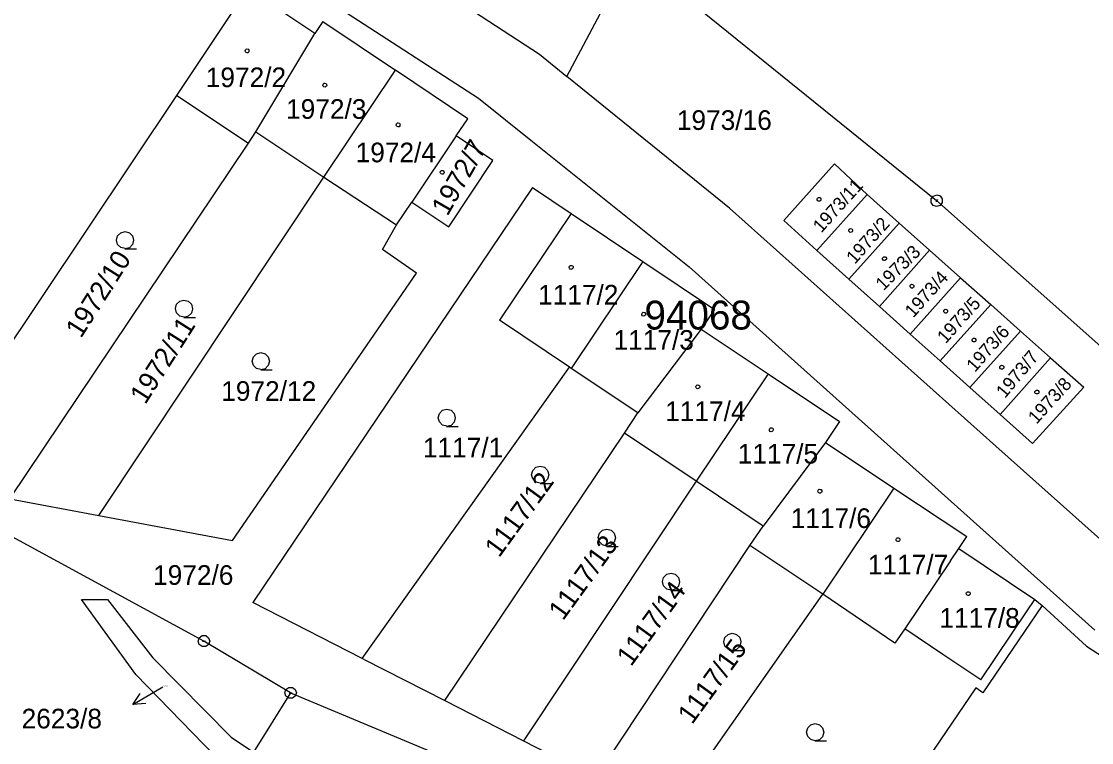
# Model space of a CAD drawing. Extents: x -806774 to -803680, y -1151731 to -1150053.
# Drawn here: x -804116.6 to -804023.9, y -1150162 to -1150099.6 of the extents above; entities that cross this region are included whole.
import ezdxf

# ---------------------------------------------------------------- set-up
doc = ezdxf.new("R2010")
doc.units = 0
for name, color, linetype in [('1', 7, 'Continuous'), ('11', 7, 'Continuous'), ('12', 7, 'Continuous'), ('2', 7, 'Continuous'), ('3', 7, 'Continuous'), ('5', 7, 'Continuous'), ('7', 7, 'Continuous'), ('8', 7, 'Continuous')]:
    doc.layers.add(name, color=color, linetype=linetype)

msp = doc.modelspace()

# ---------------------------------------------------------------- linework, layer by layer
at = {"layer": '1'}
for p, q in [((-804085.95, -1150093.17), (-804071.72, -1150102.49)), ((-804069.36, -1150104.41), (-804063.74, -1150093.81)), ((-804063.74, -1150093.81), (-804037.36, -1150115.15)), ((-804103.11, -1150106.05), (-804096.96, -1150096.81)), ((-804091.16, -1150100.68), (-804096.96, -1150096.81)), ((-804088.85, -1150098.62), (-804077.01, -1150106.29)), ((-804090.48, -1150099.66), (-804091.16, -1150100.68)), ((-804090.48, -1150099.66), (-804084.2, -1150103.85)), ((-804096.26, -1150109.2), (-804091.16, -1150100.68)), ((-804071.72, -1150102.49), (-804069.36, -1150104.41)), ((-804090.4, -1150113.11), (-804084.2, -1150103.85)), ((-804077.94, -1150108.07), (-804084.2, -1150103.85)), ((-804055.29, -1150115.8), (-804069.36, -1150104.41)), ((-804125.47, -1150139.46), (-804103.11, -1150106.05)), ((-804103.11, -1150106.05), (-804096.92, -1150110.18)), ((-804077.01, -1150106.29), (-804072.33, -1150110.03)), ((-804078.95, -1150109.54), (-804077.94, -1150108.07)), ((-804096.92, -1150110.18), (-804096.26, -1150109.2)), ((-804096.26, -1150109.2), (-804090.4, -1150113.11)), ((-804078.95, -1150109.54), (-804082.78, -1150115.28)), ((-804075.77, -1150111.67), (-804078.95, -1150109.54)), ((-804117.56, -1150140.94), (-804096.92, -1150110.18)), ((-804072.33, -1150110.03), (-804058.77, -1150120.88)), ((-804079.58, -1150117.41), (-804075.77, -1150111.67)), ((-804046.18, -1150111.95), (-804050.59, -1150116.88)), ((-804043.37, -1150114.62), (-804046.18, -1150111.95)), ((-804109.85, -1150142.39), (-804090.4, -1150113.11)), ((-804090.4, -1150113.11), (-804084.1, -1150117.24)), ((-804072.32, -1150114.01), (-804096.54, -1150149.93)), ((-804072.32, -1150114.01), (-804068.97, -1150116.26)), ((-804084.1, -1150117.24), (-804082.78, -1150115.28)), ((-804082.78, -1150115.28), (-804079.58, -1150117.41)), ((-804047.71, -1150119.47), (-804043.37, -1150114.62)), ((-804043.37, -1150114.62), (-804040.59, -1150117.09)), ((-804037.36, -1150115.15), (-804007.58, -1150141.61)), ((-804068.97, -1150116.26), (-804075.18, -1150125.5)), ((-804068.97, -1150116.26), (-804062.77, -1150120.4)), ((-804032.24, -1150136.39), (-804055.29, -1150115.8)), ((-804050.59, -1150116.88), (-804047.71, -1150119.47)), ((-804044.94, -1150121.95), (-804040.59, -1150117.09)), ((-804040.59, -1150117.09), (-804037.96, -1150119.44)), ((-804085.32, -1150119.38), (-804084.1, -1150117.24)), ((-804082.38, -1150121.42), (-804085.32, -1150119.38)), ((-804044.94, -1150121.95), (-804047.71, -1150119.47)), ((-804042.31, -1150124.31), (-804037.96, -1150119.44)), ((-804037.96, -1150119.44), (-804035.28, -1150121.82)), ((-804062.77, -1150120.4), (-804068.97, -1150129.66)), ((-804062.77, -1150120.4), (-804056.58, -1150124.56)), ((-804058.77, -1150120.88), (-804023.66, -1150152.32)), ((-804098.29, -1150144.56), (-804082.38, -1150121.42)), ((-804035.28, -1150121.82), (-804039.64, -1150126.69)), ((-804035.28, -1150121.82), (-804032.67, -1150124.14)), ((-804042.31, -1150124.31), (-804044.94, -1150121.95)), ((-804056.58, -1150124.56), (-804057.72, -1150126.26)), ((-804039.64, -1150126.69), (-804042.31, -1150124.31)), ((-804037.04, -1150129.02), (-804032.67, -1150124.14)), ((-804032.67, -1150124.14), (-804030.1, -1150126.43)), ((-804069.14, -1150129.55), (-804075.18, -1150125.5)), ((-804057.72, -1150126.26), (-804063.21, -1150133.52)), ((-804057.72, -1150126.26), (-804051.93, -1150130.14)), ((-804034.48, -1150131.31), (-804030.1, -1150126.43)), ((-804030.1, -1150126.43), (-804027.49, -1150128.76)), ((-804037.04, -1150129.02), (-804039.64, -1150126.69)), ((-804034.48, -1150131.31), (-804037.04, -1150129.02)), ((-804031.87, -1150133.65), (-804027.49, -1150128.76)), ((-804027.49, -1150128.76), (-804024.63, -1150131.29)), ((-804087.08, -1150154.76), (-804069.14, -1150129.55)), ((-804068.97, -1150129.66), (-804069.14, -1150129.55)), ((-804063.21, -1150133.52), (-804068.97, -1150129.66)), ((-804051.93, -1150130.14), (-804058.16, -1150139.43)), ((-804051.93, -1150130.14), (-804045.77, -1150134.27)), ((-804031.87, -1150133.65), (-804034.48, -1150131.31)), ((-804024.63, -1150131.29), (-804029.07, -1150136.15)), ((-804064.37, -1150135.26), (-804063.21, -1150133.52)), ((-804029.07, -1150136.15), (-804031.87, -1150133.65)), ((-804045.77, -1150134.27), (-804046.96, -1150136.06)), ((-804079.93, -1150158.41), (-804064.37, -1150135.26)), ((-804058.16, -1150139.43), (-804064.37, -1150135.26)), ((-804046.96, -1150136.06), (-804052.37, -1150143.3)), ((-804046.96, -1150136.06), (-804041.06, -1150140.02)), ((-804032.24, -1150136.39), (-804018.21, -1150148.91)), ((-804058.16, -1150139.43), (-804073.11, -1150161.88)), ((-804052.37, -1150143.3), (-804058.16, -1150139.43)), ((-804041.06, -1150140.02), (-804047.21, -1150149.2)), ((-804041.06, -1150140.02), (-804034.74, -1150144.2)), ((-804100.76, -1150153.26), (-804123.32, -1150141)), ((-804117.56, -1150140.94), (-804109.85, -1150142.39)), ((-804109.85, -1150142.39), (-804098.29, -1150144.56)), ((-804053.51, -1150144.98), (-804052.37, -1150143.3)), ((-804035.44, -1150145.25), (-804034.74, -1150144.2)), ((-804066.84, -1150165.08), (-804053.51, -1150144.98)), ((-804047.21, -1150149.2), (-804053.51, -1150144.98)), ((-804036.16, -1150146.31), (-804035.44, -1150145.25)), ((-804035.44, -1150145.25), (-804028.85, -1150149.65)), ((-804036.16, -1150146.31), (-804040.11, -1150152.2)), ((-804060.58, -1150168.28), (-804047.21, -1150149.2)), ((-804040.96, -1150153.43), (-804047.21, -1150149.2)), ((-804106.66, -1150156.14), (-804111.36, -1150149.65)), ((-804111.36, -1150149.65), (-804109.12, -1150149.65)), ((-804109.12, -1150149.65), (-804105.18, -1150154.7)), ((-804087.08, -1150154.76), (-804096.54, -1150149.93)), ((-804028.23, -1150150.17), (-804033.36, -1150157.72)), ((-804029.57, -1150150.73), (-804028.85, -1150149.65)), ((-804028.85, -1150149.65), (-804028.23, -1150150.17)), ((-804028.23, -1150150.17), (-804024.39, -1150153.7)), ((-804033.52, -1150156.62), (-804029.57, -1150150.73)), ((-804040.11, -1150152.2), (-804040.96, -1150153.43)), ((-804036.82, -1150154.41), (-804040.11, -1150152.2)), ((-804093.26, -1150157.74), (-804100.76, -1150153.26)), ((-804024.39, -1150153.7), (-804019.32, -1150156.96)), ((-804105.18, -1150154.7), (-804098.41, -1150161.58)), ((-804086.9, -1150154.85), (-804087.08, -1150154.76)), ((-804086.9, -1150154.85), (-804079.93, -1150158.41)), ((-804033.52, -1150156.62), (-804036.82, -1150154.41)), ((-804099.79, -1150163.22), (-804106.66, -1150156.14)), ((-804093.26, -1150157.74), (-804096.48, -1150162.88)), ((-804093.26, -1150157.74), (-804062.46, -1150170.59)), ((-804033.97, -1150157.29), (-804040.72, -1150167.26)), ((-804033.36, -1150157.72), (-804033.97, -1150157.29)), ((-804079.93, -1150158.41), (-804073.11, -1150161.88)), ((-804098.41, -1150161.58), (-804096.48, -1150162.88)), ((-804073.11, -1150161.88), (-804066.84, -1150165.08))]:
    msp.add_line(p, q, dxfattribs=at)
at = {"layer": '12'}
for p, q in [((-804103.11, -1150106.05), (-804096.96, -1150096.81)), ((-804103.11, -1150106.05), (-804096.96, -1150096.81)), ((-804091.16, -1150100.68), (-804096.96, -1150096.81)), ((-804090.48, -1150099.66), (-804091.16, -1150100.68)), ((-804090.48, -1150099.66), (-804084.2, -1150103.85)), ((-804096.26, -1150109.2), (-804091.16, -1150100.68)), ((-804096.26, -1150109.2), (-804091.16, -1150100.68)), ((-804090.4, -1150113.11), (-804084.2, -1150103.85)), ((-804090.4, -1150113.11), (-804084.2, -1150103.85)), ((-804077.94, -1150108.07), (-804084.2, -1150103.85)), ((-804103.11, -1150106.05), (-804096.92, -1150110.18)), ((-804078.95, -1150109.54), (-804077.94, -1150108.07)), ((-804096.92, -1150110.18), (-804096.26, -1150109.2)), ((-804096.26, -1150109.2), (-804090.4, -1150113.11)), ((-804078.95, -1150109.54), (-804082.78, -1150115.28)), ((-804078.95, -1150109.54), (-804082.78, -1150115.28)), ((-804075.77, -1150111.67), (-804078.95, -1150109.54)), ((-804079.58, -1150117.41), (-804075.77, -1150111.67)), ((-804046.18, -1150111.95), (-804050.59, -1150116.88)), ((-804043.37, -1150114.62), (-804046.18, -1150111.95)), ((-804090.4, -1150113.11), (-804084.1, -1150117.24)), ((-804084.1, -1150117.24), (-804082.78, -1150115.28)), ((-804082.78, -1150115.28), (-804079.58, -1150117.41)), ((-804047.71, -1150119.47), (-804043.37, -1150114.62)), ((-804047.71, -1150119.47), (-804043.37, -1150114.62)), ((-804043.37, -1150114.62), (-804040.59, -1150117.09)), ((-804068.97, -1150116.26), (-804075.18, -1150125.5)), ((-804068.97, -1150116.26), (-804062.77, -1150120.4)), ((-804050.59, -1150116.88), (-804047.71, -1150119.47)), ((-804044.94, -1150121.95), (-804040.59, -1150117.09)), ((-804044.94, -1150121.95), (-804040.59, -1150117.09)), ((-804040.59, -1150117.09), (-804037.96, -1150119.44)), ((-804044.94, -1150121.95), (-804047.71, -1150119.47)), ((-804042.31, -1150124.31), (-804037.96, -1150119.44)), ((-804042.31, -1150124.31), (-804037.96, -1150119.44)), ((-804037.96, -1150119.44), (-804035.28, -1150121.82)), ((-804062.77, -1150120.4), (-804068.97, -1150129.66)), ((-804062.77, -1150120.4), (-804068.97, -1150129.66)), ((-804062.77, -1150120.4), (-804056.58, -1150124.56)), ((-804035.28, -1150121.82), (-804039.64, -1150126.69)), ((-804035.28, -1150121.82), (-804039.64, -1150126.69)), ((-804035.28, -1150121.82), (-804032.67, -1150124.14)), ((-804042.31, -1150124.31), (-804044.94, -1150121.95)), ((-804056.58, -1150124.56), (-804057.72, -1150126.26)), ((-804039.64, -1150126.69), (-804042.31, -1150124.31)), ((-804037.04, -1150129.02), (-804032.67, -1150124.14)), ((-804037.04, -1150129.02), (-804032.67, -1150124.14)), ((-804032.67, -1150124.14), (-804030.1, -1150126.43)), ((-804069.14, -1150129.55), (-804075.18, -1150125.5)), ((-804057.72, -1150126.26), (-804063.21, -1150133.52)), ((-804057.72, -1150126.26), (-804063.21, -1150133.52)), ((-804057.72, -1150126.26), (-804051.93, -1150130.14)), ((-804034.48, -1150131.31), (-804030.1, -1150126.43)), ((-804034.48, -1150131.31), (-804030.1, -1150126.43)), ((-804030.1, -1150126.43), (-804027.49, -1150128.76)), ((-804037.04, -1150129.02), (-804039.64, -1150126.69)), ((-804034.48, -1150131.31), (-804037.04, -1150129.02)), ((-804031.87, -1150133.65), (-804027.49, -1150128.76)), ((-804031.87, -1150133.65), (-804027.49, -1150128.76)), ((-804027.49, -1150128.76), (-804024.63, -1150131.29)), ((-804068.97, -1150129.66), (-804069.14, -1150129.55)), ((-804063.21, -1150133.52), (-804068.97, -1150129.66)), ((-804051.93, -1150130.14), (-804058.16, -1150139.43)), ((-804051.93, -1150130.14), (-804058.16, -1150139.43)), ((-804051.93, -1150130.14), (-804045.77, -1150134.27)), ((-804031.87, -1150133.65), (-804034.48, -1150131.31)), ((-804024.63, -1150131.29), (-804029.07, -1150136.15)), ((-804064.37, -1150135.26), (-804063.21, -1150133.52)), ((-804029.07, -1150136.15), (-804031.87, -1150133.65)), ((-804045.77, -1150134.27), (-804046.96, -1150136.06)), ((-804058.16, -1150139.43), (-804064.37, -1150135.26)), ((-804046.96, -1150136.06), (-804052.37, -1150143.3)), ((-804046.96, -1150136.06), (-804052.37, -1150143.3)), ((-804046.96, -1150136.06), (-804041.06, -1150140.02)), ((-804052.37, -1150143.3), (-804058.16, -1150139.43)), ((-804041.06, -1150140.02), (-804047.21, -1150149.2)), ((-804041.06, -1150140.02), (-804047.21, -1150149.2)), ((-804041.06, -1150140.02), (-804034.74, -1150144.2)), ((-804053.51, -1150144.98), (-804052.37, -1150143.3)), ((-804035.44, -1150145.25), (-804034.74, -1150144.2)), ((-804047.21, -1150149.2), (-804053.51, -1150144.98)), ((-804036.16, -1150146.31), (-804035.44, -1150145.25)), ((-804036.16, -1150146.31), (-804035.44, -1150145.25)), ((-804035.44, -1150145.25), (-804028.85, -1150149.65)), ((-804036.16, -1150146.31), (-804040.11, -1150152.2)), ((-804036.16, -1150146.31), (-804040.11, -1150152.2)), ((-804040.96, -1150153.43), (-804047.21, -1150149.2)), ((-804029.57, -1150150.73), (-804028.85, -1150149.65)), ((-804033.52, -1150156.62), (-804029.57, -1150150.73)), ((-804040.11, -1150152.2), (-804040.96, -1150153.43)), ((-804036.82, -1150154.41), (-804040.11, -1150152.2)), ((-804033.52, -1150156.62), (-804036.82, -1150154.41))]:
    msp.add_line(p, q, dxfattribs=at)
at = {"layer": '3'}
for points in [[(-804107.58, -1150119.3), (-804107.96, -1150119.2), (-804108.23, -1150118.93), (-804108.33, -1150118.56), (-804108.23, -1150118.19), (-804107.96, -1150117.92), (-804107.59, -1150117.82), (-804107.22, -1150117.92), (-804106.95, -1150118.19), (-804106.85, -1150118.57), (-804106.95, -1150118.95), (-804107.22, -1150119.22), (-804107.6, -1150119.32), (-804106.6, -1150119.32)], [(-804102.48, -1150125.23), (-804102.86, -1150125.13), (-804103.13, -1150124.86), (-804103.23, -1150124.49), (-804103.13, -1150124.12), (-804102.86, -1150123.85), (-804102.49, -1150123.75), (-804102.12, -1150123.85), (-804101.85, -1150124.12), (-804101.75, -1150124.5), (-804101.85, -1150124.88), (-804102.12, -1150125.15), (-804102.5, -1150125.25), (-804101.5, -1150125.25)], [(-804095.83, -1150129.77), (-804096.21, -1150129.67), (-804096.48, -1150129.4), (-804096.58, -1150129.03), (-804096.48, -1150128.66), (-804096.21, -1150128.39), (-804095.84, -1150128.29), (-804095.47, -1150128.39), (-804095.2, -1150128.66), (-804095.1, -1150129.04), (-804095.2, -1150129.42), (-804095.47, -1150129.69), (-804095.85, -1150129.79), (-804094.85, -1150129.79)], [(-804079.74, -1150134.67), (-804080.12, -1150134.57), (-804080.39, -1150134.3), (-804080.49, -1150133.93), (-804080.39, -1150133.56), (-804080.12, -1150133.29), (-804079.75, -1150133.19), (-804079.38, -1150133.29), (-804079.11, -1150133.56), (-804079.01, -1150133.94), (-804079.11, -1150134.32), (-804079.38, -1150134.59), (-804079.76, -1150134.69), (-804078.76, -1150134.69)], [(-804071.66, -1150139.6), (-804072.04, -1150139.5), (-804072.31, -1150139.23), (-804072.41, -1150138.86), (-804072.31, -1150138.49), (-804072.04, -1150138.22), (-804071.67, -1150138.12), (-804071.3, -1150138.22), (-804071.03, -1150138.49), (-804070.93, -1150138.87), (-804071.03, -1150139.25), (-804071.3, -1150139.52), (-804071.68, -1150139.62), (-804070.68, -1150139.62)], [(-804065.89, -1150145.04), (-804066.27, -1150144.94), (-804066.54, -1150144.67), (-804066.64, -1150144.3), (-804066.54, -1150143.93), (-804066.27, -1150143.66), (-804065.9, -1150143.56), (-804065.53, -1150143.66), (-804065.26, -1150143.93), (-804065.16, -1150144.31), (-804065.26, -1150144.69), (-804065.53, -1150144.96), (-804065.91, -1150145.06), (-804064.91, -1150145.06)], [(-804060.33, -1150148.85), (-804060.71, -1150148.75), (-804060.98, -1150148.48), (-804061.08, -1150148.11), (-804060.98, -1150147.74), (-804060.71, -1150147.47), (-804060.34, -1150147.37), (-804059.97, -1150147.47), (-804059.7, -1150147.74), (-804059.6, -1150148.12), (-804059.7, -1150148.5), (-804059.97, -1150148.77), (-804060.35, -1150148.87), (-804059.35, -1150148.87)], [(-804055.03, -1150154.06), (-804055.41, -1150153.96), (-804055.68, -1150153.69), (-804055.78, -1150153.32), (-804055.68, -1150152.95), (-804055.41, -1150152.68), (-804055.04, -1150152.58), (-804054.67, -1150152.68), (-804054.4, -1150152.95), (-804054.3, -1150153.33), (-804054.4, -1150153.71), (-804054.67, -1150153.98), (-804055.05, -1150154.08), (-804054.05, -1150154.08)], [(-804047.86, -1150161.88), (-804048.24, -1150161.78), (-804048.51, -1150161.51), (-804048.61, -1150161.14), (-804048.51, -1150160.77), (-804048.24, -1150160.5), (-804047.87, -1150160.4), (-804047.5, -1150160.5), (-804047.23, -1150160.77), (-804047.13, -1150161.15), (-804047.23, -1150161.53), (-804047.5, -1150161.8), (-804047.88, -1150161.9), (-804046.88, -1150161.9)]]:
    msp.add_lwpolyline(points, dxfattribs=at)
at = {"layer": '5'}
for points in [[(-804097.03, -1150102.02), (-804096.93, -1150102.04), (-804096.88, -1150102.13), (-804096.86, -1150102.19), (-804096.88, -1150102.28), (-804096.96, -1150102.35), (-804097.03, -1150102.36), (-804097.12, -1150102.33), (-804097.18, -1150102.27), (-804097.2, -1150102.19), (-804097.18, -1150102.1), (-804097.1, -1150102.03)], [(-804090.3, -1150104.98), (-804090.2, -1150105), (-804090.15, -1150105.09), (-804090.13, -1150105.15), (-804090.15, -1150105.24), (-804090.23, -1150105.31), (-804090.3, -1150105.32), (-804090.39, -1150105.29), (-804090.45, -1150105.23), (-804090.47, -1150105.15), (-804090.45, -1150105.06), (-804090.37, -1150104.99)], [(-804083.95, -1150108.42), (-804083.85, -1150108.44), (-804083.8, -1150108.53), (-804083.78, -1150108.59), (-804083.8, -1150108.68), (-804083.88, -1150108.75), (-804083.95, -1150108.76), (-804084.04, -1150108.73), (-804084.1, -1150108.67), (-804084.12, -1150108.59), (-804084.1, -1150108.5), (-804084.02, -1150108.43)], [(-804080.14, -1150112.53), (-804080.04, -1150112.55), (-804079.99, -1150112.64), (-804079.97, -1150112.7), (-804079.99, -1150112.79), (-804080.07, -1150112.86), (-804080.14, -1150112.87), (-804080.23, -1150112.84), (-804080.29, -1150112.78), (-804080.31, -1150112.7), (-804080.29, -1150112.61), (-804080.21, -1150112.54)], [(-804047.657, -1150114.928), (-804047.576, -1150114.866), (-804047.476, -1150114.888), (-804047.418, -1150114.913), (-804047.363, -1150114.987), (-804047.364, -1150115.093), (-804047.403, -1150115.152), (-804047.485, -1150115.2), (-804047.569, -1150115.205), (-804047.642, -1150115.167), (-804047.697, -1150115.093), (-804047.696, -1150114.987)], [(-804044.917, -1150117.618), (-804044.836, -1150117.556), (-804044.736, -1150117.578), (-804044.678, -1150117.603), (-804044.623, -1150117.677), (-804044.624, -1150117.783), (-804044.663, -1150117.842), (-804044.745, -1150117.89), (-804044.829, -1150117.895), (-804044.902, -1150117.857), (-804044.957, -1150117.783), (-804044.956, -1150117.677)], [(-804069.119, -1150120.832), (-804069.045, -1150120.762), (-804068.943, -1150120.773), (-804068.882, -1150120.791), (-804068.82, -1150120.859), (-804068.809, -1150120.965), (-804068.841, -1150121.028), (-804068.917, -1150121.084), (-804069.001, -1150121.099), (-804069.078, -1150121.069), (-804069.14, -1150121.001), (-804069.151, -1150120.895)], [(-804041.997, -1150120.058), (-804041.916, -1150119.996), (-804041.816, -1150120.018), (-804041.758, -1150120.043), (-804041.703, -1150120.117), (-804041.704, -1150120.223), (-804041.743, -1150120.282), (-804041.825, -1150120.33), (-804041.909, -1150120.335), (-804041.982, -1150120.297), (-804042.037, -1150120.223), (-804042.036, -1150120.117)], [(-804039.617, -1150122.438), (-804039.536, -1150122.376), (-804039.436, -1150122.398), (-804039.378, -1150122.423), (-804039.323, -1150122.497), (-804039.324, -1150122.603), (-804039.363, -1150122.662), (-804039.445, -1150122.71), (-804039.529, -1150122.715), (-804039.602, -1150122.677), (-804039.657, -1150122.603), (-804039.656, -1150122.497)], [(-804036.697, -1150124.598), (-804036.616, -1150124.536), (-804036.516, -1150124.558), (-804036.458, -1150124.583), (-804036.403, -1150124.657), (-804036.404, -1150124.763), (-804036.443, -1150124.822), (-804036.525, -1150124.87), (-804036.609, -1150124.875), (-804036.682, -1150124.837), (-804036.737, -1150124.763), (-804036.736, -1150124.657)], [(-804062.839, -1150124.872), (-804062.765, -1150124.802), (-804062.663, -1150124.813), (-804062.602, -1150124.831), (-804062.54, -1150124.899), (-804062.529, -1150125.005), (-804062.561, -1150125.068), (-804062.637, -1150125.124), (-804062.721, -1150125.139), (-804062.798, -1150125.109), (-804062.86, -1150125.041), (-804062.871, -1150124.935)], [(-804034.247, -1150127.098), (-804034.166, -1150127.036), (-804034.066, -1150127.058), (-804034.008, -1150127.083), (-804033.953, -1150127.157), (-804033.954, -1150127.263), (-804033.993, -1150127.322), (-804034.075, -1150127.37), (-804034.159, -1150127.375), (-804034.232, -1150127.337), (-804034.287, -1150127.263), (-804034.286, -1150127.157)], [(-804031.837, -1150129.448), (-804031.756, -1150129.386), (-804031.656, -1150129.408), (-804031.598, -1150129.433), (-804031.543, -1150129.507), (-804031.544, -1150129.613), (-804031.583, -1150129.672), (-804031.665, -1150129.72), (-804031.749, -1150129.725), (-804031.822, -1150129.687), (-804031.877, -1150129.613), (-804031.876, -1150129.507)], [(-804058.159, -1150131.162), (-804058.085, -1150131.092), (-804057.983, -1150131.103), (-804057.922, -1150131.121), (-804057.86, -1150131.189), (-804057.849, -1150131.295), (-804057.881, -1150131.358), (-804057.957, -1150131.414), (-804058.041, -1150131.429), (-804058.118, -1150131.399), (-804058.18, -1150131.331), (-804058.191, -1150131.225)], [(-804028.807, -1150131.598), (-804028.726, -1150131.536), (-804028.626, -1150131.558), (-804028.568, -1150131.583), (-804028.513, -1150131.657), (-804028.514, -1150131.763), (-804028.553, -1150131.822), (-804028.635, -1150131.87), (-804028.719, -1150131.875), (-804028.792, -1150131.837), (-804028.847, -1150131.763), (-804028.846, -1150131.657)], [(-804051.799, -1150134.872), (-804051.725, -1150134.802), (-804051.623, -1150134.813), (-804051.562, -1150134.831), (-804051.5, -1150134.899), (-804051.489, -1150135.005), (-804051.521, -1150135.068), (-804051.597, -1150135.124), (-804051.681, -1150135.139), (-804051.758, -1150135.109), (-804051.82, -1150135.041), (-804051.831, -1150134.935)], [(-804047.599, -1150140.192), (-804047.525, -1150140.122), (-804047.423, -1150140.133), (-804047.362, -1150140.151), (-804047.3, -1150140.219), (-804047.289, -1150140.325), (-804047.321, -1150140.388), (-804047.397, -1150140.444), (-804047.481, -1150140.459), (-804047.558, -1150140.429), (-804047.62, -1150140.361), (-804047.631, -1150140.255)], [(-804040.839, -1150144.382), (-804040.765, -1150144.312), (-804040.663, -1150144.323), (-804040.602, -1150144.341), (-804040.54, -1150144.409), (-804040.529, -1150144.515), (-804040.561, -1150144.578), (-804040.637, -1150144.634), (-804040.721, -1150144.649), (-804040.798, -1150144.619), (-804040.86, -1150144.551), (-804040.871, -1150144.445)], [(-804034.759, -1150149.052), (-804034.685, -1150148.982), (-804034.583, -1150148.993), (-804034.522, -1150149.011), (-804034.46, -1150149.079), (-804034.449, -1150149.185), (-804034.481, -1150149.248), (-804034.557, -1150149.304), (-804034.641, -1150149.319), (-804034.718, -1150149.289), (-804034.78, -1150149.221), (-804034.791, -1150149.115)]]:
    msp.add_lwpolyline(points, close=True, dxfattribs=at)
at = {"layer": '7'}
msp.add_line((-804106.905, -1150158.732), (-804104.32, -1150157.21), dxfattribs=at)
msp.add_lwpolyline([(-804105.79, -1150158.656), (-804106.905, -1150158.732), (-804106.297, -1150157.794)], dxfattribs=at)
at = {"layer": '8'}
for p, q in [((-804037.289, -1150115.053), (-804037.431, -1150115.247)), ((-804100.88, -1150153.26), (-804100.64, -1150153.26)), ((-804093.38, -1150157.739), (-804093.14, -1150157.741))]:
    msp.add_line(p, q, dxfattribs=at)
for points in [[(-804037.062, -1150115.555), (-804037.355, -1150115.65), (-804037.648, -1150115.559), (-804037.822, -1150115.307), (-804037.82, -1150114.999), (-804037.636, -1150114.749), (-804037.343, -1150114.654), (-804037.05, -1150114.745), (-804036.876, -1150114.997), (-804036.878, -1150115.305)], [(-804100.61, -1150152.78), (-804100.36, -1150152.96), (-804100.26, -1150153.25), (-804100.36, -1150153.54), (-804100.61, -1150153.72), (-804100.92, -1150153.72), (-804101.17, -1150153.54), (-804101.27, -1150153.25), (-804101.17, -1150152.96), (-804100.92, -1150152.78)], [(-804093.108, -1150157.261), (-804092.858, -1150157.442), (-804092.76, -1150157.733), (-804092.861, -1150158.022), (-804093.112, -1150158.201), (-804093.422, -1150158.199), (-804093.671, -1150158.018), (-804093.77, -1150157.727), (-804093.668, -1150157.438), (-804093.418, -1150157.259)]]:
    msp.add_lwpolyline(points, close=True, dxfattribs=at)

# ---------------------------------------------------------------- texts
at = {"layer": '11'}
msp.add_text('94068', height=2.5, dxfattribs=at).set_placement((-804062.638, -1150126.3))
at = {"layer": '2'}
for s, height, p in [('1972/2', 1.7, (-804100.607, -1150105.33)), ('1972/3', 1.7, (-804093.657, -1150108.07)), ('1973/16', 1.7, (-804059.837, -1150109.03)), ('1972/4', 1.7, (-804087.637, -1150111.83)), ('1117/2', 1.7, (-804071.847, -1150124.14)), ('1117/3', 1.7, (-804065.317, -1150128.05)), ('1972/12', 1.7, (-804099.267, -1150132.47)), ('1117/4', 1.7, (-804060.847, -1150134.22)), ('1117/1', 1.7, (-804081.817, -1150137.37)), ('1117/5', 1.7, (-804054.567, -1150137.9)), ('1117/6', 1.7, (-804049.987, -1150143.47)), ('1117/7', 1.7, (-804043.307, -1150147.49)), ('1972/6', 1.7, (-804105.167, -1150148.39)), ('1117/8', 1.7, (-804037.117, -1150152.1)), ('2623/8', 0.1, (-804104.306, -1150157.21))]:
    msp.add_text(s, height=height, dxfattribs=at).set_placement(p)
for s, height, rotation, p in [('1972/7', 1.7, 60.10327, (-804079.694, -1150116.56)), ('1973/11', 1.14, 47.89927, (-804047.333, -1150117.995)), ('1973/2', 1.14, 48.35764, (-804044.435, -1150120.703)), ('1972/10', 1.7, 57.58226, (-804111.409, -1150127.128)), ('1973/3', 1.14, 44.97719, (-804041.954, -1150122.994)), ('1973/4', 1.14, 48.18575, (-804039.374, -1150125.344)), ('1973/5', 1.14, 48.24305, (-804036.575, -1150127.584)), ('1972/11', 1.7, 57.58226, (-804105.839, -1150132.858)), ('1973/6', 1.14, 48.816, (-804034.037, -1150130.052)), ('1973/7', 1.14, 50.1911, (-804031.441, -1150132.308)), ('1973/8', 1.14, 47.84198, (-804028.713, -1150134.545)), ('1117/12', 1.7, 53.97262, (-804075.219, -1150146.102)), ('1117/13', 1.7, 53.97262, (-804069.689, -1150151.552)), ('1117/14', 1.7, 53.97262, (-804063.799, -1150155.522)), ('1117/15', 1.7, 53.97262, (-804058.519, -1150160.542))]:
    msp.add_text(s, height=height, rotation=rotation, dxfattribs=at).set_placement(p)
at = {"layer": '7'}
msp.add_text('2623/8', height=1.7, dxfattribs=at).set_placement((-804116.542, -1150160.81))

doc.saveas('drawing.dxf')
